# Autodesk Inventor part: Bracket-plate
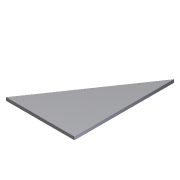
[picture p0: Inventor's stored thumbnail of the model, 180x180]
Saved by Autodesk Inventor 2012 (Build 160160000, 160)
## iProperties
Shininess: 64.0
Length Units: 11269
Angle Units: 11279
Time Units: 11290
Mass Units: 11283
Length Display Precision: 3
Angle Display Precision: 2
Compacted: True
Part Number: Bracket-plate
Document SubType Name: Modeling
Created: 2003-01
Designer: Owner
Density: 1 g/cm^3
Material: Default
Density: 0.0
Volumn: 0.0
Area: 0.0
PropertySet Name: Model Information
Control State: 0
Master: False
Checked Out: False
Author: Owner
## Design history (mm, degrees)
sketch "Sketch1"
  geometry: L1 (-27.627, 0.004)-(-0.127, 0.004); L2 (-0.127, 0.004)-(-0.127, 40.004); L3 (-0.127, 40.004)-(-27.627, 0.004)
  constraints: 6 end point, 1 horizontal, 1 perpendicular
  dimensions: "d0" = 27.5 distance of L1.start L1.end; "d1" = 40 distance of L1.end L2.end
extrude "Extrusion1" new body sketch "Sketch1" distance "d2" = 1.25; taper "d3" = 0 deg
body "Solid1"
